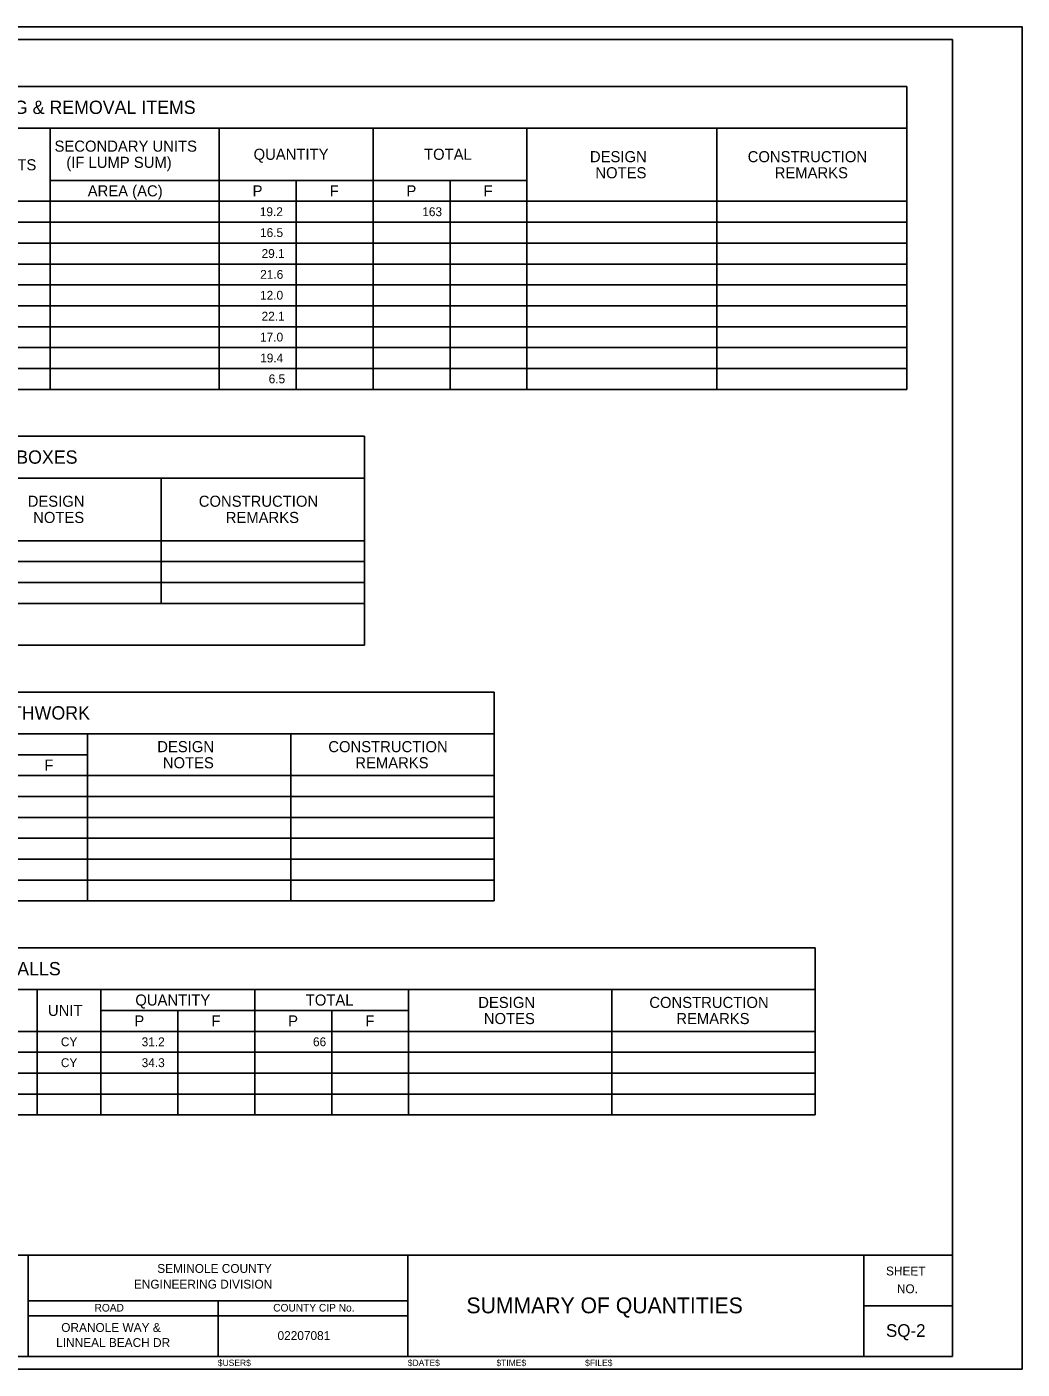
# Model space of a CAD drawing. Extents: x -831.4 to -734.9, y -2212.7 to -2202.1.
# Drawn here: x -802.75 to -794.89, y -2212.74 to -2202.14 of the extents above; entities that cross this region are included whole.
import ezdxf

# ---------------------------------------------------------------- set-up
doc = ezdxf.new("R2010")
doc.units = 0
for name, color, linetype in [('PlotBorder_dp', 7, 'Continuous'), ('SheetBorder_dp', 7, 'Continuous'), ('SheetLines_dp', 7, 'Continuous'), ('SumBoxBorder_dp', 7, 'Continuous'), ('SumBoxLines_dp', 7, 'Continuous'), ('SumBoxLinesMin_dp', 7, 'Continuous'), ('TextLabel', 7, 'Continuous'), ('TextMinor', 7, 'Continuous'), ('TextMisc', 7, 'Continuous'), ('TextShtNo', 7, 'Continuous')]:
    doc.layers.add(name, color=color, linetype=linetype)

msp = doc.modelspace()

# ---------------------------------------------------------------- linework, layer by layer
at = {"layer": 'PlotBorder_dp'}
msp.add_lwpolyline([(-811.391, -2212.74), (-794.891, -2212.74), (-794.891, -2202.14), (-811.391, -2202.14)], close=True, dxfattribs=at)
at = {"layer": 'SheetBorder_dp'}
for p, q in [((-810.841, -2202.24), (-795.441, -2202.24)), ((-795.441, -2202.24), (-795.441, -2212.64)), ((-810.841, -2211.84), (-795.441, -2211.84)), ((-810.841, -2212.64), (-795.441, -2212.64))]:
    msp.add_line(p, q, dxfattribs=at)
at = {"layer": 'SheetLines_dp'}
for p, q in [((-802.741, -2211.84), (-802.741, -2212.64)), ((-799.741, -2212.64), (-799.741, -2211.84)), ((-796.141, -2212.64), (-796.141, -2211.84)), ((-802.741, -2212.2), (-799.741, -2212.2)), ((-801.241, -2212.2), (-801.241, -2212.64)), ((-802.741, -2212.32), (-799.741, -2212.32)), ((-796.141, -2212.24), (-795.441, -2212.24))]:
    msp.add_line(p, q, dxfattribs=at)
at = {"layer": 'SumBoxBorder_dp'}
for p, q in [((-810.479, -2202.61), (-795.802, -2202.61)), ((-795.802, -2202.61), (-795.802, -2205.003)), ((-810.479, -2205.003), (-795.802, -2205.003)), ((-806.197, -2205.373), (-800.084, -2205.373)), ((-800.084, -2205.373), (-800.084, -2207.023)), ((-806.197, -2207.023), (-800.084, -2207.023)), ((-807.221, -2207.393), (-799.061, -2207.393)), ((-799.061, -2207.393), (-799.061, -2209.043)), ((-807.221, -2209.043), (-799.061, -2209.043)), ((-809.756, -2209.413), (-796.526, -2209.413)), ((-796.526, -2209.413), (-796.526, -2210.733)), ((-809.756, -2210.733), (-796.526, -2210.733))]:
    msp.add_line(p, q, dxfattribs=at)
at = {"layer": 'SumBoxLines_dp'}
for p, q in [((-810.479, -2202.94), (-795.802, -2202.94)), ((-802.567, -2202.94), (-802.567, -2205.003)), ((-802.567, -2202.94), (-802.567, -2203.353)), ((-801.232, -2202.94), (-801.232, -2205.003)), ((-801.232, -2202.94), (-801.232, -2205.003)), ((-800.017, -2202.94), (-800.017, -2205.003)), ((-800.017, -2202.94), (-800.017, -2205.003)), ((-798.802, -2202.94), (-798.802, -2205.003)), ((-798.802, -2202.94), (-798.802, -2205.003)), ((-797.302, -2202.94), (-797.302, -2205.003)), ((-797.302, -2202.94), (-797.302, -2205.003)), ((-802.567, -2203.353), (-798.802, -2203.353)), ((-802.567, -2203.353), (-798.802, -2203.353)), ((-810.479, -2203.518), (-795.802, -2203.518)), ((-810.479, -2203.518), (-795.802, -2203.518)), ((-802.567, -2203.518), (-802.567, -2205.003)), ((-806.197, -2205.703), (-800.084, -2205.703)), ((-801.689, -2205.703), (-801.689, -2206.693)), ((-801.689, -2205.703), (-801.689, -2206.693)), ((-806.197, -2206.198), (-800.084, -2206.198)), ((-806.197, -2206.198), (-800.084, -2206.198)), ((-803.294, -2206.693), (-800.084, -2206.693)), ((-807.221, -2207.723), (-799.061, -2207.723)), ((-802.271, -2207.723), (-802.271, -2209.043)), ((-800.666, -2207.723), (-800.666, -2209.043)), ((-800.666, -2207.723), (-800.666, -2209.043)), ((-803.486, -2207.888), (-802.271, -2207.888)), ((-803.486, -2207.888), (-802.271, -2207.888)), ((-802.271, -2207.888), (-802.271, -2209.043)), ((-807.221, -2208.053), (-799.061, -2208.053)), ((-807.221, -2208.053), (-799.061, -2208.053)), ((-809.756, -2209.743), (-796.526, -2209.743)), ((-809.756, -2209.743), (-796.526, -2209.743)), ((-802.668, -2209.743), (-802.668, -2210.733)), ((-802.668, -2209.743), (-802.668, -2210.733)), ((-802.166, -2209.743), (-802.166, -2210.733)), ((-802.166, -2209.743), (-802.166, -2210.733)), ((-800.951, -2209.743), (-800.951, -2210.073)), ((-800.951, -2209.743), (-800.951, -2210.733)), ((-799.736, -2209.743), (-799.736, -2210.733)), ((-799.736, -2209.743), (-799.736, -2210.733)), ((-798.131, -2209.743), (-798.131, -2210.733)), ((-798.131, -2209.743), (-798.131, -2210.733)), ((-802.166, -2209.908), (-800.951, -2209.908)), ((-802.166, -2209.908), (-799.736, -2209.908)), ((-809.756, -2210.073), (-796.526, -2210.073))]:
    msp.add_line(p, q, dxfattribs=at)
at = {"layer": 'SumBoxLinesMin_dp'}
for p, q in [((-802.567, -2203.353), (-802.567, -2203.518)), ((-800.624, -2203.353), (-800.624, -2205.003)), ((-800.624, -2203.353), (-800.624, -2205.003)), ((-799.409, -2203.353), (-799.409, -2205.003)), ((-799.409, -2203.353), (-799.409, -2205.003)), ((-810.479, -2203.683), (-795.802, -2203.683)), ((-810.479, -2203.683), (-795.802, -2203.683)), ((-810.479, -2203.848), (-795.802, -2203.848)), ((-810.479, -2204.013), (-795.802, -2204.013)), ((-797.302, -2204.013), (-795.802, -2204.013)), ((-810.479, -2204.178), (-797.302, -2204.178)), ((-810.479, -2204.178), (-795.802, -2204.178)), ((-810.479, -2204.343), (-795.802, -2204.343)), ((-797.302, -2204.343), (-795.802, -2204.343)), ((-810.479, -2204.508), (-797.302, -2204.508)), ((-810.479, -2204.508), (-795.802, -2204.508)), ((-810.479, -2204.673), (-795.802, -2204.673)), ((-797.302, -2204.673), (-795.802, -2204.673)), ((-810.479, -2204.838), (-797.302, -2204.838)), ((-810.479, -2204.838), (-795.802, -2204.838)), ((-806.197, -2206.363), (-800.084, -2206.363)), ((-806.197, -2206.363), (-800.084, -2206.363)), ((-806.197, -2206.528), (-800.084, -2206.528)), ((-806.197, -2206.528), (-800.084, -2206.528)), ((-807.221, -2208.218), (-799.061, -2208.218)), ((-807.221, -2208.218), (-799.061, -2208.218)), ((-807.221, -2208.383), (-799.061, -2208.383)), ((-807.221, -2208.383), (-799.061, -2208.383)), ((-807.221, -2208.548), (-799.061, -2208.548)), ((-807.221, -2208.548), (-799.061, -2208.548)), ((-807.221, -2208.713), (-799.061, -2208.713)), ((-807.221, -2208.713), (-799.061, -2208.713)), ((-807.221, -2208.878), (-799.061, -2208.878)), ((-807.221, -2208.878), (-799.061, -2208.878)), ((-801.558, -2209.908), (-801.558, -2210.733)), ((-801.558, -2209.908), (-801.558, -2210.733)), ((-800.343, -2209.908), (-800.343, -2210.733)), ((-800.343, -2209.908), (-800.343, -2210.733)), ((-809.756, -2210.238), (-796.526, -2210.238)), ((-809.756, -2210.238), (-796.526, -2210.238)), ((-809.756, -2210.403), (-796.526, -2210.403)), ((-809.756, -2210.403), (-796.526, -2210.403)), ((-809.756, -2210.568), (-796.526, -2210.568)), ((-809.756, -2210.568), (-796.526, -2210.568))]:
    msp.add_line(p, q, dxfattribs=at)

# ---------------------------------------------------------------- texts
at = {"layer": 'TextLabel'}
for s, height, p in [('SUMMARY OF CLEARING AND GRUBBING & REMOVAL ITEMS', 0.105, (-805.576, -2202.828)), ('SECONDARY UNITS', 0.0875, (-802.532, -2203.126)), ('QUANTITY', 0.0875, (-800.96, -2203.19)), ('TOTAL', 0.0875, (-799.614, -2203.19)), ('UNITS', 0.0875, (-803.027, -2203.273)), ('(IF LUMP SUM)', 0.0875, (-802.439, -2203.254)), ('DESIGN', 0.0875, (-798.304, -2203.209)), ('CONSTRUCTION', 0.0875, (-797.058, -2203.209)), ('NOTES', 0.0875, (-798.261, -2203.336)), ('REMARKS', 0.0875, (-796.845, -2203.336)), ('AREA (AC)', 0.0875, (-802.27, -2203.479)), ('P', 0.0875, (-800.968, -2203.479)), ('F', 0.0875, (-800.359, -2203.479)), ('P', 0.0875, (-799.753, -2203.479)), ('F', 0.0875, (-799.144, -2203.479)), ('19.2', 0.07, (-800.911, -2203.635)), ('163', 0.07, (-799.628, -2203.635)), ('16.5', 0.07, (-800.909, -2203.8)), ('29.1', 0.07, (-800.897, -2203.965)), ('21.6', 0.07, (-800.908, -2204.13)), ('12.0', 0.07, (-800.909, -2204.295)), ('22.1', 0.07, (-800.897, -2204.46)), ('17.0', 0.07, (-800.909, -2204.625)), ('19.4', 0.07, (-800.908, -2204.79)), ('6.5', 0.07, (-800.841, -2204.955)), ('SUMMARY OF MAILBOXES', 0.105, (-804.153, -2205.59)), ('DESIGN', 0.0875, (-802.744, -2205.93)), ('CONSTRUCTION', 0.0875, (-801.393, -2205.93)), ('NOTES', 0.0875, (-802.701, -2206.058)), ('REMARKS', 0.0875, (-801.18, -2206.058)), ('SUMMARY OF EARTHWORK', 0.105, (-804.156, -2207.61)), ('DESIGN', 0.0875, (-801.721, -2207.868)), ('CONSTRUCTION', 0.0875, (-800.37, -2207.868)), ('F', 0.0875, (-802.613, -2208.014)), ('NOTES', 0.0875, (-801.677, -2207.995)), ('REMARKS', 0.0875, (-800.157, -2207.995)), ('SUMMARY OF WALLS', 0.105, (-803.95, -2209.63)), ('QUANTITY', 0.0875, (-801.894, -2209.869)), ('TOTAL', 0.0875, (-800.548, -2209.869)), ('UNIT', 0.0875, (-802.584, -2209.951)), ('DESIGN', 0.0875, (-799.186, -2209.888)), ('CONSTRUCTION', 0.0875, (-797.835, -2209.888)), ('P', 0.0875, (-801.902, -2210.034)), ('F', 0.0875, (-801.293, -2210.034)), ('P', 0.0875, (-800.687, -2210.034)), ('F', 0.0875, (-800.078, -2210.034)), ('NOTES', 0.0875, (-799.142, -2210.015)), ('REMARKS', 0.0875, (-797.622, -2210.015)), ('CY', 0.07, (-802.482, -2210.19)), ('31.2', 0.07, (-801.844, -2210.19)), ('66', 0.07, (-800.491, -2210.19)), ('CY', 0.07, (-802.482, -2210.355)), ('34.3', 0.07, (-801.844, -2210.355))]:
    msp.add_text(s, height=height, dxfattribs=at).set_placement(p)
at = {"layer": 'TextMinor'}
for s, p in [('$USER$', (-801.242, -2212.715)), ('$DATE$', (-799.742, -2212.715)), ('$TIME$', (-799.042, -2212.715)), ('$FILE$', (-798.342, -2212.715))]:
    msp.add_text(s, height=0.05, rotation=360, dxfattribs=at).set_placement(p)
at = {"layer": 'TextMisc'}
for s, height, rotation, p in [('SEMINOLE COUNTY', 0.07, 360, (-801.721, -2211.98)), ('SHEET', 0.07, 359.8607, (-795.966, -2212)), ('ENGINEERING DIVISION', 0.07, 360, (-801.905, -2212.104)), ('NO.', 0.07, 359.8607, (-795.88, -2212.14)), ('ROAD', 0.06, 360, (-802.216, -2212.285)), ('COUNTY CIP No.', 0.06, 360, (-800.805, -2212.285)), ('ORANOLE WAY & ', 0.07, 360, (-802.479, -2212.446)), (' LINNEAL BEACH DR', 0.07, 360, (-802.545, -2212.565)), ('   02207081   ', 0.07, 360, (-800.849, -2212.51))]:
    msp.add_text(s, height=height, rotation=rotation, dxfattribs=at).set_placement(p)
msp.add_text('SUMMARY OF QUANTITIES', height=0.125, dxfattribs=at).set_placement((-799.279, -2212.299))
at = {"layer": 'TextShtNo'}
msp.add_text('SQ-2', height=0.1, dxfattribs=at).set_placement((-795.966, -2212.485))

doc.saveas('drawing.dxf')
